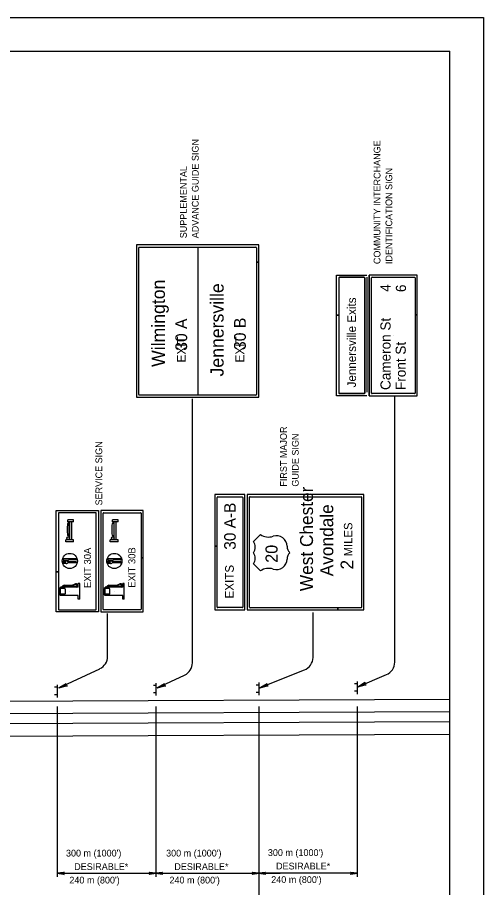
# Model space of a CAD drawing. Extents: x 640994 to 644422, y 298458 to 299646.
# Drawn here: x 644151 to 644358.3, y 299258.5 to 299645.6 of the extents above; entities that cross this region are included whole.
import ezdxf

# ---------------------------------------------------------------- set-up
doc = ezdxf.new("R2010")
doc.units = 0
for name, color, linetype in [('1', 7, 'Continuous'), ('2', 7, 'Continuous'), ('XCS-GRID-MIN', 7, 'Continuous')]:
    doc.layers.add(name, color=color, linetype=linetype)

msp = doc.modelspace()

# ---------------------------------------------------------------- linework, layer by layer
at = {"layer": '1'}
for p in [(643557.31, 299630.63), (644343.31, 299066.63)]:
    msp.add_line(p, (644343.31, 299630.63), dxfattribs=at)
at = {"layer": '2'}
for p, q in [((644258.31, 299544.39), (644203.94, 299544.39)), ((644203.94, 299544.39), (644203.94, 299476.64)), ((644258.31, 299536.79), (644258.31, 299544.39)), ((644204.94, 299477.89), (644204.94, 299543.14)), ((644205.19, 299543.39), (644257.06, 299543.39)), ((644231.19, 299543.39), (644231.19, 299477.64)), ((644257.31, 299543.14), (644257.31, 299536.79)), ((644258.31, 299536.79), (644257.31, 299536.79)), ((644257.31, 299536.79), (644257.31, 299477.89)), ((644257.31, 299536.79), (644258.31, 299536.79)), ((644258.31, 299476.64), (644258.31, 299536.79)), ((644292.94, 299513.21), (644292.94, 299531.02)), ((644292.94, 299531.02), (644306.44, 299531.02)), ((644293.94, 299529.77), (644293.94, 299513.21)), ((644294.19, 299530.02), (644305.19, 299530.02)), ((644305.19, 299530.02), (644294.19, 299530.02)), ((644305.44, 299529.77), (644305.44, 299478.52)), ((644305.44, 299478.52), (644305.44, 299529.77)), ((644306.44, 299530.14), (644306.44, 299478.89)), ((644307.44, 299477.27), (644307.44, 299531.02)), ((644328.81, 299531.02), (644307.44, 299531.02)), ((644307.44, 299531.02), (644307.44, 299477.27)), ((644308.44, 299478.52), (644308.44, 299529.77)), ((644308.44, 299478.52), (644308.44, 299529.77)), ((644308.69, 299530.02), (644327.56, 299530.02)), ((644308.69, 299530.02), (644327.56, 299530.02)), ((644327.81, 299529.77), (644327.81, 299513.28)), ((644328.81, 299513.28), (644328.81, 299531.02)), ((644292.94, 299513.21), (644293.94, 299513.21)), ((644293.94, 299513.21), (644292.94, 299513.21)), ((644292.94, 299477.27), (644292.94, 299513.21)), ((644293.94, 299513.21), (644293.94, 299478.52)), ((644299.69, 299515.27), (644299.69, 299515.27)), ((644327.81, 299513.28), (644328.81, 299513.28)), ((644328.81, 299513.28), (644327.81, 299513.28)), ((644327.81, 299513.28), (644327.81, 299478.52)), ((644328.81, 299477.27), (644328.81, 299513.28)), ((644318.19, 299504.14), (644318.19, 299504.14)), ((644257.06, 299477.64), (644205.19, 299477.64)), ((644305.19, 299478.27), (644294.19, 299478.27)), ((644294.19, 299478.27), (644305.19, 299478.27)), ((644327.56, 299478.27), (644308.69, 299478.27)), ((644327.56, 299478.27), (644308.69, 299478.27)), ((644203.94, 299476.64), (644258.31, 299476.64)), ((644228.81, 299358.52), (644228.81, 299475.89)), ((644306.44, 299477.27), (644292.94, 299477.27)), ((644307.44, 299477.27), (644307.41, 299477.27)), ((644307.44, 299477.27), (644328.81, 299477.27)), ((644318.81, 299358.77), (644318.81, 299476.77)), ((644252.19, 299433.34), (644238.81, 299433.34)), ((644238.81, 299433.34), (644238.81, 299410.41)), ((644239.81, 299410.41), (644239.81, 299432.09)), ((644240.06, 299432.34), (644250.94, 299432.34)), ((644251.19, 299432.09), (644251.19, 299383.31)), ((644252.19, 299382.06), (644252.19, 299433.34)), ((644305.06, 299433.39), (644253.19, 299433.39)), ((644253.19, 299433.39), (644253.19, 299382.02)), ((644254.19, 299383.27), (644254.19, 299432.14)), ((644254.44, 299432.39), (644303.81, 299432.39)), ((644304.06, 299432.14), (644304.06, 299383.27)), ((644305.06, 299382.02), (644305.06, 299433.39)), ((644168.19, 299399.01), (644168.19, 299426.27)), ((644168.19, 299426.27), (644187.06, 299426.27)), ((644169.19, 299425.02), (644169.19, 299399.01)), ((644185.81, 299425.27), (644169.44, 299425.27)), ((644186.06, 299382.39), (644186.06, 299425.02)), ((644187.06, 299426.27), (644187.06, 299381.14)), ((644206.94, 299426.27), (644188.06, 299426.27)), ((644188.06, 299426.27), (644188.06, 299381.14)), ((644189.06, 299382.39), (644189.06, 299425.02)), ((644189.31, 299425.27), (644205.69, 299425.27)), ((644205.94, 299425.02), (644205.94, 299405.17)), ((644206.94, 299405.17), (644206.94, 299426.27)), ((644175.94, 299422.14), (644173.44, 299422.14)), ((644173.44, 299421.27), (644173.44, 299422.14)), ((644175.94, 299421.27), (644173.44, 299421.27)), ((644174.06, 299414.77), (644174.06, 299421.02)), ((644174.31, 299413.27), (644174.31, 299421.27)), ((644175.19, 299413.27), (644175.19, 299421.27)), ((644175.94, 299421.27), (644175.94, 299422.14)), ((644195.81, 299422.14), (644193.31, 299422.14)), ((644193.31, 299421.27), (644193.31, 299422.14)), ((644195.81, 299421.27), (644193.31, 299421.27)), ((644193.94, 299414.77), (644193.94, 299421.02)), ((644194.06, 299413.27), (644194.06, 299421.27)), ((644194.94, 299413.27), (644194.94, 299421.27)), ((644195.81, 299421.27), (644195.81, 299422.14)), ((644174.31, 299417.27), (644174.31, 299417.27)), ((644174.31, 299417.27), (644174.31, 299417.27)), ((644194.06, 299417.27), (644194.06, 299417.27)), ((644194.06, 299417.27), (644194.06, 299417.27)), ((644175.94, 299413.27), (644172.44, 299413.27)), ((644172.44, 299412.27), (644172.44, 299413.27)), ((644175.94, 299412.27), (644172.44, 299412.27)), ((644175.94, 299412.27), (644175.94, 299413.27)), ((644195.81, 299413.27), (644192.19, 299413.27)), ((644192.19, 299412.27), (644192.19, 299413.27)), ((644195.81, 299412.27), (644192.19, 299412.27)), ((644195.81, 299412.27), (644195.81, 299413.27)), ((644255.94, 299412.52), (644259.06, 299415.64)), ((644266.19, 299415.02), (644266.19, 299415.02)), ((644239.81, 299410.41), (644238.81, 299410.41)), ((644238.81, 299410.41), (644238.81, 299382.06)), ((644238.81, 299410.41), (644239.81, 299410.41)), ((644239.81, 299383.31), (644239.81, 299410.41)), ((644270.94, 299410.39), (644270.94, 299410.39)), ((644177.06, 299404.77), (644171.31, 299404.77)), ((644171.31, 299404.77), (644171.31, 299404.39)), ((644177.06, 299404.27), (644174.06, 299404.27)), ((644196.81, 299404.77), (644191.06, 299404.77)), ((644191.06, 299404.77), (644191.06, 299404.39)), ((644196.81, 299404.27), (644193.94, 299404.27)), ((644205.94, 299405.17), (644206.94, 299405.17)), ((644206.94, 299405.17), (644205.94, 299405.17)), ((644205.94, 299405.17), (644205.94, 299382.39)), ((644206.94, 299381.14), (644206.94, 299405.17)), ((644264.19, 299407.52), (644264.19, 299407.52)), ((644264.19, 299407.52), (644264.19, 299407.52)), ((644270.94, 299404.64), (644270.94, 299404.64)), ((644171.19, 299403.52), (644172.44, 299403.77)), ((644172.56, 299403.52), (644171.19, 299403.52)), ((644171.19, 299403.02), (644172.31, 299403.14)), ((644172.69, 299402.89), (644171.19, 299403.02)), ((644172.56, 299402.64), (644171.19, 299402.89)), ((644171.19, 299402.89), (644172.69, 299402.89)), ((644171.31, 299403.39), (644172.56, 299403.52)), ((644172.56, 299403.27), (644171.31, 299403.39)), ((644173.44, 299404.02), (644171.81, 299404.02)), ((644172.31, 299403.14), (644172.56, 299403.27)), ((644177.06, 299403.39), (644173.56, 299403.39)), ((644177.06, 299403.02), (644173.56, 299403.02)), ((644174.31, 299403.77), (644174.31, 299403.77)), ((644174.31, 299403.77), (644174.31, 299403.77)), ((644177.69, 299403.77), (644177.69, 299403.77)), ((644191.06, 299403.52), (644192.19, 299403.77)), ((644191.06, 299403.39), (644192.44, 299403.52)), ((644192.44, 299403.52), (644191.06, 299403.52)), ((644192.44, 299403.27), (644191.06, 299403.39)), ((644191.06, 299403.02), (644192.19, 299403.14)), ((644192.44, 299402.89), (644191.06, 299403.02)), ((644192.31, 299402.64), (644191.06, 299402.89)), ((644191.06, 299402.89), (644192.44, 299402.89)), ((644193.19, 299404.02), (644191.56, 299404.02)), ((644192.19, 299403.14), (644192.44, 299403.27)), ((644196.81, 299403.39), (644193.31, 299403.39)), ((644196.81, 299403.02), (644193.31, 299403.02)), ((644194.06, 299403.77), (644194.06, 299403.77)), ((644194.06, 299403.77), (644194.06, 299403.77)), ((644197.44, 299403.77), (644197.44, 299403.77)), ((644259.06, 299399.39), (644255.94, 299402.52)), ((644168.19, 299381.14), (644168.19, 299399.01)), ((644168.19, 299399.01), (644169.19, 299399.01)), ((644169.19, 299399.01), (644168.19, 299399.01)), ((644169.19, 299399.01), (644169.19, 299382.39)), ((644170.56, 299392.14), (644171.19, 299392.77)), ((644171.81, 299393.02), (644174.94, 299393.02)), ((644172.06, 299392.77), (644174.94, 299392.77)), ((644172.06, 299392.77), (644172.06, 299392.27)), ((644173.44, 299392.52), (644176.81, 299392.52)), ((644175.56, 299393.14), (644176.44, 299393.52)), ((644175.81, 299392.89), (644176.56, 299393.14)), ((644178.06, 299392.14), (644178.06, 299393.77)), ((644178.69, 299393.77), (644178.06, 299393.77)), ((644178.69, 299386.77), (644178.69, 299393.77)), ((644190.44, 299392.14), (644191.06, 299392.77)), ((644191.56, 299393.02), (644194.81, 299393.02)), ((644191.81, 299392.77), (644194.81, 299392.77)), ((644191.81, 299392.77), (644191.81, 299392.27)), ((644193.31, 299392.52), (644196.56, 299392.52)), ((644195.44, 299393.14), (644196.19, 299393.52)), ((644195.56, 299392.89), (644196.31, 299393.14)), ((644197.81, 299392.14), (644197.81, 299393.77)), ((644198.44, 299393.77), (644197.81, 299393.77)), ((644198.44, 299386.77), (644198.44, 299393.77)), ((644169.81, 299389.02), (644169.81, 299391.64)), ((644178.06, 299392.14), (644170.06, 299392.14)), ((644170.19, 299389.27), (644170.19, 299391.39)), ((644171.94, 299391.64), (644170.44, 299391.64)), ((644171.94, 299389.02), (644170.44, 299389.02)), ((644172.06, 299392.27), (644171.19, 299392.27)), ((644171.19, 299392.27), (644171.19, 299392.14)), ((644172.31, 299389.27), (644172.31, 299391.27)), ((644173.19, 299392.14), (644173.19, 299392.27)), ((644173.44, 299392.14), (644173.44, 299392.14)), ((644173.56, 299392.27), (644177.06, 299392.27)), ((644174.31, 299390.39), (644174.31, 299390.39)), ((644174.31, 299390.39), (644174.31, 299390.39)), ((644189.56, 299389.02), (644189.56, 299391.64)), ((644197.81, 299392.14), (644189.94, 299392.14)), ((644190.06, 299389.27), (644190.06, 299391.39)), ((644191.81, 299391.64), (644190.19, 299391.64)), ((644191.81, 299389.02), (644190.19, 299389.02)), ((644191.06, 299392.27), (644190.94, 299392.14)), ((644191.81, 299392.27), (644191.06, 299392.27)), ((644192.06, 299389.27), (644192.06, 299391.27)), ((644192.94, 299392.14), (644192.94, 299392.27)), ((644193.31, 299392.14), (644193.31, 299392.14)), ((644193.44, 299392.27), (644196.94, 299392.27)), ((644194.06, 299390.39), (644194.06, 299390.39)), ((644194.06, 299390.39), (644194.06, 299390.39)), ((644178.06, 299388.52), (644170.06, 299388.52)), ((644178.06, 299386.77), (644178.06, 299388.52)), ((644178.69, 299386.77), (644178.06, 299386.77)), ((644197.81, 299388.52), (644189.94, 299388.52)), ((644197.81, 299386.77), (644197.81, 299388.52)), ((644198.44, 299386.77), (644197.81, 299386.77)), ((644187.06, 299381.14), (644168.19, 299381.14)), ((644169.44, 299382.14), (644185.81, 299382.14)), ((644188.06, 299381.14), (644206.94, 299381.14)), ((644205.69, 299382.14), (644189.31, 299382.14)), ((644238.81, 299382.06), (644252.19, 299382.06)), ((644250.94, 299383.06), (644240.06, 299383.06)), ((644253.19, 299382.02), (644293.51, 299382.02)), ((644293.51, 299383.02), (644254.44, 299383.02)), ((644282.44, 299360.89), (644282.44, 299380.89)), ((644293.51, 299383.02), (644293.51, 299382.02)), ((644293.51, 299382.02), (644293.51, 299383.02)), ((644303.81, 299383.02), (644293.51, 299383.02)), ((644293.51, 299382.02), (644305.06, 299382.02)), ((644191.06, 299361.39), (644191.06, 299380.52)), ((644169.44, 299347.39), (644187.56, 299355.89)), ((644259.69, 299347.89), (644278.69, 299355.39)), ((644213.19, 299347.39), (644225.31, 299353.02)), ((644302.06, 299350.27), (644302.06, 299344.64)), ((644302.31, 299347.89), (644315.19, 299353.27)), ((644168.69, 299347.64), (644167.44, 299347.64)), ((644168.69, 299348.77), (644168.69, 299343.14)), ((644212.56, 299348.39), (644211.44, 299348.39)), ((644212.56, 299349.52), (644212.56, 299344.02)), ((644258.31, 299348.64), (644257.19, 299348.64)), ((644258.31, 299349.77), (644258.31, 299344.14)), ((644302.06, 299349.14), (644300.94, 299349.14)), ((644343.31, 299342.27), (643974.31, 299340.64)), ((644168.69, 299344.27), (644167.44, 299344.27)), ((644212.56, 299345.14), (644211.44, 299345.14)), ((644258.31, 299345.27), (644257.19, 299345.27)), ((644302.06, 299345.89), (644300.94, 299345.89)), ((644168.69, 299339.02), (644168.69, 299263.39)), ((644212.56, 299339.02), (644212.56, 299263.39)), ((644258.31, 299339.02), (644258.31, 299263.39)), ((644302.06, 299339.02), (644302.06, 299263.39)), ((644343.31, 299336.65), (643825.94, 299334.39)), ((644343.31, 299332.27), (643825.19, 299329.89)), ((644343.31, 299326.65), (643987.69, 299325.02)), ((644319.69, 299326.52), (644319.69, 299326.52)), ((644258.31, 299314.64), (644258.31, 299236.52)), ((644168.69, 299264.89), (644212.56, 299264.89)), ((644212.56, 299264.89), (644258.31, 299264.89)), ((644302.06, 299264.89), (644258.31, 299264.89)), ((644258.31, 299264.89), (644267.81, 299264.89))]:
    msp.add_line(p, q, dxfattribs=at)
for points in [[(644305.69, 299348.77), (644305.56, 299349.02), (644302.31, 299347.89), (644305.69, 299348.77), (644306.06, 299348.77), (644302.31, 299347.89), (644305.31, 299349.39), (644305.44, 299349.64), (644302.31, 299347.89), (644305.56, 299349.89), (644305.44, 299349.64)], [(644172.81, 299348.27), (644172.69, 299348.52), (644169.44, 299347.39), (644172.81, 299348.27), (644173.19, 299348.27), (644169.44, 299347.39), (644172.44, 299348.89), (644172.56, 299349.14), (644169.44, 299347.39), (644172.69, 299349.39), (644172.56, 299349.14)], [(644216.56, 299348.27), (644216.44, 299348.52), (644213.19, 299347.39), (644216.56, 299348.27), (644216.94, 299348.27), (644213.19, 299347.39), (644216.19, 299348.89), (644216.31, 299349.14), (644213.19, 299347.39), (644216.44, 299349.39), (644216.31, 299349.14)], [(644262.19, 299348.27), (644262.06, 299348.52), (644258.81, 299347.39), (644262.19, 299348.27), (644262.56, 299348.27), (644258.81, 299347.39), (644261.81, 299348.89), (644261.94, 299349.14), (644258.81, 299347.39), (644262.06, 299349.39), (644261.94, 299349.14)], [(644171.54, 299264.53), (644171.43, 299264.74), (644168.69, 299264.89), (644171.54, 299264.53), (644171.69, 299264.41), (644168.69, 299264.89), (644171.43, 299265.03), (644171.53, 299265.23), (644168.69, 299264.89), (644171.69, 299265.37), (644171.53, 299265.23)], [(644209.71, 299265.25), (644209.81, 299265.04), (644212.56, 299264.89), (644209.71, 299265.25), (644209.56, 299265.37), (644212.56, 299264.89), (644209.82, 299264.76), (644209.72, 299264.55), (644212.56, 299264.89), (644209.56, 299264.41), (644209.72, 299264.55)], [(644215.42, 299264.53), (644215.31, 299264.74), (644212.56, 299264.89), (644215.42, 299264.53), (644215.56, 299264.41), (644212.56, 299264.89), (644215.31, 299265.03), (644215.41, 299265.23), (644212.56, 299264.89), (644215.56, 299265.37), (644215.41, 299265.23)], [(644255.46, 299265.25), (644255.56, 299265.04), (644258.31, 299264.89), (644255.46, 299265.25), (644255.31, 299265.37), (644258.31, 299264.89), (644255.57, 299264.76), (644255.47, 299264.55), (644258.31, 299264.89), (644255.31, 299264.41), (644255.47, 299264.55)], [(644261.17, 299264.53), (644261.06, 299264.74), (644258.31, 299264.89), (644261.17, 299264.53), (644261.31, 299264.41), (644258.31, 299264.89), (644261.06, 299265.03), (644261.16, 299265.23), (644258.31, 299264.89), (644261.31, 299265.37), (644261.16, 299265.23)], [(644299.21, 299265.25), (644299.31, 299265.04), (644302.06, 299264.89), (644299.21, 299265.25), (644299.06, 299265.37), (644302.06, 299264.89), (644299.32, 299264.76), (644299.22, 299264.55), (644302.06, 299264.89), (644299.06, 299264.41), (644299.22, 299264.55)]]:
    msp.add_lwpolyline(points, dxfattribs=at)
for centre, radius in [((644173.54, 299413.99), 0.598), ((644193.35, 299413.99), 0.598), ((644174.27, 299403.83), 3.38), ((644194.08, 299403.83), 3.38)]:
    msp.add_circle(centre, radius, dxfattribs=at)
for centre, radius, start, end in [((644205.19, 299543.14), 0.25, 90, 180), ((644257.06, 299543.14), 0.25, 0, 90), ((644294.19, 299529.77), 0.25, 90, 180), ((644294.19, 299529.77), 0.25, 90, 180), ((644305.19, 299529.77), 0.25, 0, 90), ((644305.19, 299529.77), 0.25, 0, 90), ((644308.69, 299529.77), 0.25, 90, 180), ((644308.69, 299529.77), 0.25, 90, 180), ((644327.56, 299529.77), 0.25, 0, 90), ((644327.56, 299529.77), 0.25, 0, 90), ((644205.19, 299477.89), 0.25, 180, 270), ((644257.06, 299477.89), 0.25, 270, 0), ((644294.19, 299478.52), 0.25, 180, 270), ((644294.19, 299478.52), 0.25, 180, 270), ((644305.19, 299478.52), 0.25, 270, 0), ((644305.19, 299478.52), 0.25, 270, 0), ((644308.69, 299478.52), 0.25, 180, 270), ((644308.69, 299478.52), 0.25, 180, 270), ((644327.56, 299478.52), 0.25, 270, 0), ((644327.56, 299478.52), 0.25, 270, 0), ((644240.06, 299432.09), 0.25, 90, 180), ((644250.94, 299432.09), 0.25, 0, 90), ((644254.44, 299432.14), 0.25, 90, 180), ((644303.81, 299432.14), 0.25, 0, 90), ((644169.44, 299425.02), 0.25, 90, 180), ((644185.81, 299425.02), 0.25, 0, 90), ((644189.31, 299425.02), 0.25, 90, 180), ((644205.69, 299425.02), 0.25, 0, 90), ((644188.64, 299417.98), 15.54, 171.2295, 181.1783), ((644174.02, 299420.26), 0.74, 84.1655, 172.9293), ((644208.45, 299417.98), 15.54, 171.2295, 181.1783), ((644193.83, 299420.26), 0.74, 84.1655, 172.9293), ((644191.86, 299417.93), 18.75, 180.8408, 188.1781), ((644211.67, 299417.93), 18.75, 180.8408, 188.1781), ((644174.1, 299415.6), 0.868, 202.8419, 269.9082), ((644193.91, 299415.6), 0.868, 202.8419, 269.9082), ((644252.6, 299410.01), 4.18, 323.136, 36.864), ((644262.74, 299420.97), 6.5, 235.4253, 288.1711), ((644266.25, 299410.37), 4.66, 0.0047, 108.548), ((644274.85, 299410.37), 3.94, 180, 226.2725), ((644171.76, 299404.44), 0.422, 180, 270), ((644173.25, 299404.7), 0.696, 281.1263, 314.137), ((644174.01, 299403.95), 0.369, 83.1408, 137.1102), ((644177.09, 299404.53), 0.218, 261.5053, 98.4947), ((644191.57, 299404.44), 0.422, 180, 270), ((644193.06, 299404.7), 0.696, 281.1263, 314.137), ((644193.82, 299403.95), 0.369, 83.1408, 137.1102), ((644196.9, 299404.53), 0.218, 261.5053, 98.4947), ((644252.6, 299405), 4.18, 323.136, 36.864), ((644266.25, 299404.64), 4.66, 251.452, 359.9953), ((644274.85, 299404.64), 3.94, 133.7275, 180), ((644172.64, 299402.94), 0.83, 44.7019, 103.537), ((644172.7, 299403.37), 0.724, 261.5401, 313.94), ((644173.58, 299402.53), 0.494, 95.8318, 139.6318), ((644173.53, 299403.82), 0.42, 224.9301, 269.654), ((644177.1, 299403.21), 0.195, 258.6255, 101.3745), ((644192.45, 299402.94), 0.83, 44.7019, 103.537), ((644192.51, 299403.37), 0.724, 261.5401, 313.94), ((644193.39, 299402.53), 0.494, 95.8318, 139.6318), ((644193.34, 299403.82), 0.42, 224.9301, 269.654), ((644196.91, 299403.21), 0.195, 258.6255, 101.3745), ((644262.74, 299394.05), 6.5, 71.8289, 124.5747), ((644171.85, 299392.2), 0.826, 95.5404, 137.2088), ((644173.45, 299392.25), 0.265, 89.4256, 167.8581), ((644174.73, 299395.49), 2.48, 276.6108, 292.2765), ((644174.73, 299395.49), 2.79, 276.6108, 292.2765), ((644177.37, 299391.45), 2.24, 92.3973, 115.3499), ((644177.14, 299391.97), 1.32, 82.2446, 117.6633), ((644176.71, 299393.79), 1.27, 271.1053, 299.4807), ((644177.12, 299393.02), 0.794, 269.2148, 356.6422), ((644177.22, 299392.98), 0.7, 359.2139, 85.3444), ((644177.23, 299392.98), 0.318, 289.9687, 73.0966), ((644191.66, 299392.2), 0.826, 95.5404, 137.2088), ((644193.26, 299392.25), 0.265, 89.4256, 167.8581), ((644194.54, 299395.49), 2.48, 276.6108, 292.2765), ((644194.54, 299395.49), 2.79, 276.6108, 292.2765), ((644197.18, 299391.45), 2.24, 92.3973, 115.3499), ((644196.95, 299391.97), 1.32, 82.2446, 117.6633), ((644196.52, 299393.79), 1.27, 271.1053, 299.4807), ((644196.93, 299393.02), 0.794, 269.2148, 356.6422), ((644197.03, 299392.98), 0.7, 359.2139, 85.3444), ((644197.04, 299392.98), 0.318, 289.9687, 73.0966), ((644170.17, 299391.67), 0.405, 97.9024, 178.9277), ((644170.11, 299388.93), 0.346, 171.6254, 276.5874), ((644170.41, 299389.23), 0.207, 168.286, 258.2569), ((644170.44, 299391.42), 0.228, 107.0861, 183.3769), ((644171.92, 299391.32), 0.327, 355.7148, 73.5391), ((644171.98, 299389.28), 0.262, 276.241, 356.6554), ((644173.54, 299392.16), 0.0642, 79.1965, 181.8396), ((644189.98, 299391.67), 0.405, 97.9024, 178.9277), ((644189.92, 299388.93), 0.346, 171.6254, 276.5874), ((644190.25, 299391.42), 0.228, 107.0861, 183.3769), ((644190.22, 299389.23), 0.207, 168.286, 258.2569), ((644191.73, 299391.32), 0.327, 355.7148, 73.5391), ((644191.8, 299389.28), 0.262, 276.241, 356.6554), ((644193.36, 299392.16), 0.0642, 79.1965, 181.8396), ((644169.44, 299382.39), 0.25, 180, 270), ((644185.81, 299382.39), 0.25, 270, 0), ((644189.31, 299382.39), 0.25, 180, 270), ((644205.69, 299382.39), 0.25, 270, 0), ((644240.06, 299383.31), 0.25, 180, 270), ((644250.94, 299383.31), 0.25, 270, 0), ((644254.44, 299383.27), 0.25, 180, 270), ((644303.81, 299383.27), 0.25, 270, 0), ((644185.06, 299361.35), 6, 295.1448, 0), ((644222.81, 299358.5), 6, 295.1077, 0), ((644276.44, 299360.92), 6, 291.4477, 0), ((644312.81, 299358.79), 6, 292.6938, 0)]:
    msp.add_arc(centre, radius, start, end, dxfattribs=at)
at = {"layer": 'XCS-GRID-MIN'}
msp.add_lwpolyline([(643517.31, 299645.63), (644358.31, 299645.63), (644358.31, 299051.63), (643517.31, 299051.63)], close=True, dxfattribs=at)

# ---------------------------------------------------------------- texts
at = {"layer": '2'}
for s, height, p in [('ADVANCE GUIDE SIGN', 3, (644231.56, 299547.39)), ('COMMUNITY INTERCHANGE', 3, (644312.44, 299535.89)), ('SUPPLEMENTAL', 3, (644226.31, 299547.39)), ('IDENTIFICATION SIGN', 3, (644317.69, 299535.89)), ('Wilmington', 5.875, (644216.56, 299490.14)), ('Jennersville', 5.8747, (644242.69, 299485.89)), (' 4', 4.5, (644316.94, 299521.89)), (' 6', 4.5, (644323.81, 299521.77)), ('Jennersville Exits', 3.8752, (644301.56, 299481.02)), ('     30 A', 5.21, (644226.45, 299487.65)), ('     30 B', 5.25, (644252.56, 299487.89)), ('Cameron St     ', 4.5, (644316.94, 299479.89)), ('EXIT    ', 3.918, (644225.83, 299492.12)), ('EXIT    ', 3.918, (644251.83, 299492.12)), ('Front St       ', 4.5, (644323.69, 299479.89)), ('FIRST MAJOR', 3, (644270.81, 299436.89)), ('GUIDE SIGN', 3, (644276.06, 299436.89)), ('SERVICE SIGN', 3, (644188.69, 299428.52)), ('West Chester', 5.7435, (644282.44, 299390.39)), ('30 A-B', 5.125, (644248.06, 299408.82)), ('Avondale', 5.743, (644291.44, 299397.02)), ('MILES', 3.75, (644299.94, 299405.89)), ('EXIT 30A', 3.134, (644183.69, 299391.79)), ('EXIT 30B', 3.134, (644203.44, 299391.97)), ('20', 5.375, (644266.69, 299403.02)), ('EXITS', 3.875, (644247.21, 299387.12)), ('2', 5.74, (644300.44, 299400.02))]:
    msp.add_text(s, height=height, rotation=90, dxfattribs=at).set_placement(p)
for s, p in [("300 m (1000')", (644172.57, 299272.36)), ("300 m (1000')", (644217.1, 299272.36)), ("300 m (1000')", (644262.36, 299272.6)), ('DESIRABLE*', (644176.22, 299266.36)), ('DESIRABLE*', (644220.75, 299266.36)), ('DESIRABLE*', (644266.01, 299266.6)), ("240 m (800')", (644174.07, 299260.36)), ("240 m (800')", (644218.6, 299260.36)), ("240 m (800')", (644263.86, 299260.6))]:
    msp.add_text(s, height=3, dxfattribs=at).set_placement(p)

doc.saveas('drawing.dxf')
